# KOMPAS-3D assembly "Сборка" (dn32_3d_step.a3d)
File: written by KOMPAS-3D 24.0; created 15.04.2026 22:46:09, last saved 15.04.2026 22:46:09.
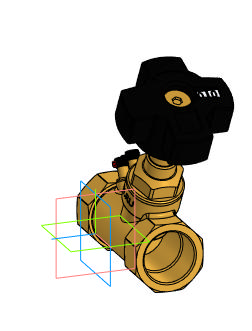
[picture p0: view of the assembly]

Document properties: Автор: tyuri; Полное имя файла: D:\Аутсорс\VB0000P-T Клапан балансировочный статический DN.ru\DN32\Исходные данные\dn32_3d_step.a3d

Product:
- Component [detail]: Деталь1  | qty 1  | Автор: tyuri; source file: Деталь1 - Деталь1.m3d
- Component [detail]: Деталь2  | qty 1  | Автор: tyuri; source file: Деталь2 - Деталь2.m3d
- Part/product: Сборка

Referenced files in D:\Аутсорс\VB0000P-T Клапан балансировочный статический DN.ru\DN32\Исходные данные\: Деталь1 - Деталь1.m3d, Деталь2 - Деталь2.m3d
